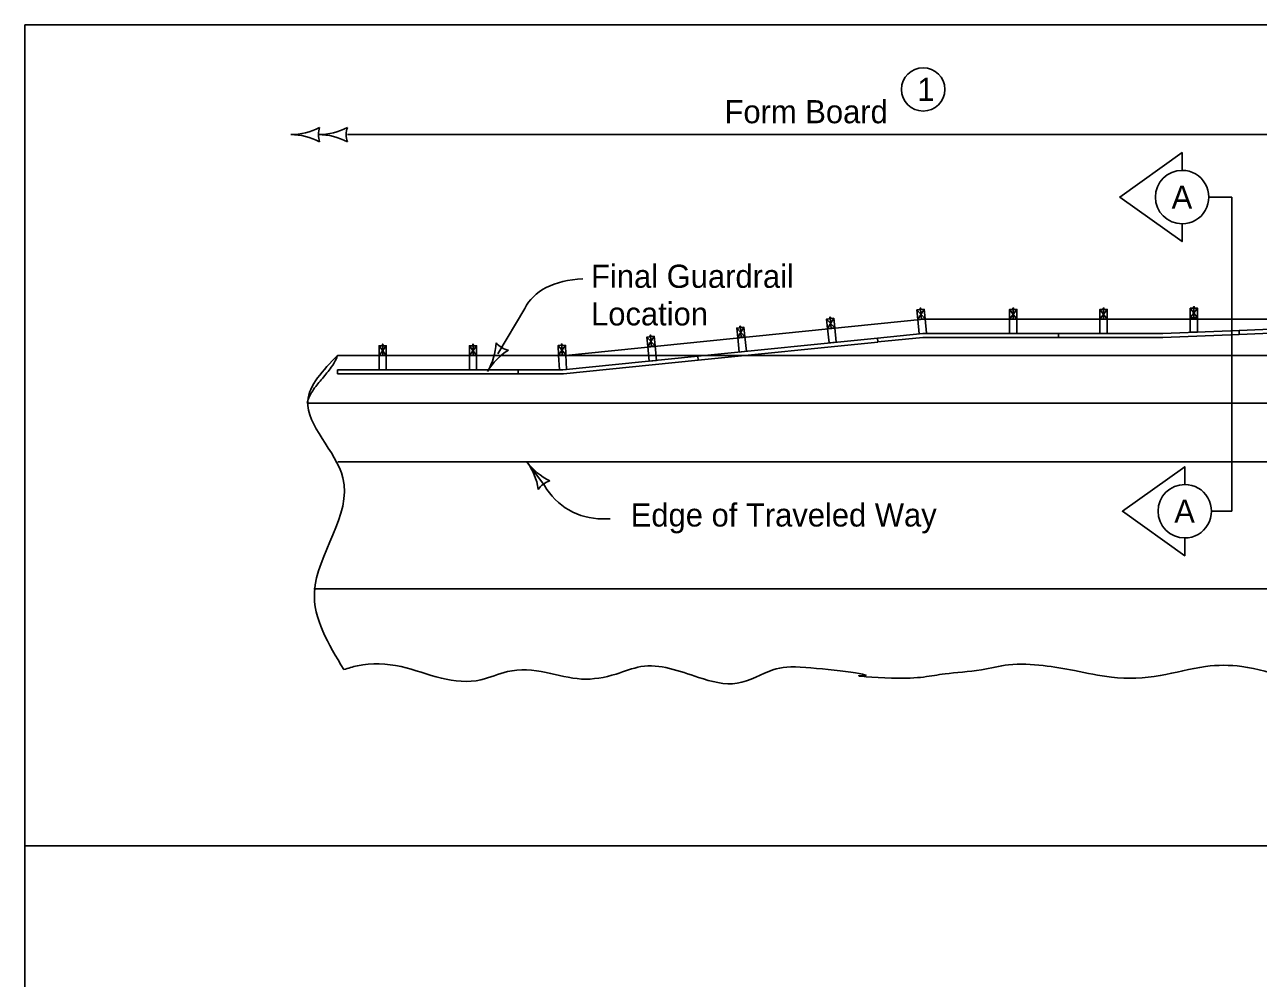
# Model space of a CAD drawing. Extents: x 6410 to 81668, y 3928 to 11667.
# Drawn here: x 6410 to 7264, y 9265 to 9924 of the extents above; entities that cross this region are included whole.
import ezdxf

# ---------------------------------------------------------------- set-up
doc = ezdxf.new("R2010")
doc.units = 0
for name, color, linetype in [('dsnCellElements', 7, 'Continuous'), ('dsnNonPlotable', 7, 'Continuous'), ('dsnShtPlotShapeBatchPrint', 7, 'Continuous'), ('dsnStdBlockModified', 7, 'Continuous'), ('Level 10', 7, 'Continuous'), ('Level 11', 7, 'Continuous'), ('Level 14', 7, 'Continuous'), ('Level 7', 7, 'Continuous')]:
    doc.layers.add(name, color=color, linetype=linetype)

msp = doc.modelspace()

# ---------------------------------------------------------------- linework, layer by layer
at = {"layer": 'dsnCellElements'}
for p, q in [((6756.43, 9728.01), (6737.88, 9696.66)), ((6756.43, 9728.01), (6737.88, 9696.66)), ((6770.05, 9605.55), (6757.93, 9622)), ((6770.05, 9605.55), (6757.93, 9622)), ((6810.13, 9582.48), (6815.58, 9582.48)), ((6810.13, 9582.48), (6815.58, 9582.48))]:
    msp.add_line(p, q, dxfattribs=at)
for centre, radius, start, end in [((6694.12, 9706.16), 42.5, 329.37973, 357.45222), ((6694.12, 9706.16), 42.5, 329.37973, 357.45222), ((6767.26, 9662.87), 42.5, 121.30724, 149.37973), ((6767.26, 9662.87), 42.5, 121.30724, 149.37973), ((6748.84, 9715.18), 16.42, 221.64638, 257.11308), ((6748.84, 9715.18), 16.42, 221.64638, 257.11308), ((6792.15, 9647.21), 42.5, 216.37256, 244.44505), ((6723.71, 9596.8), 42.5, 8.30007, 36.37256), ((6792.15, 9647.21), 42.5, 216.37256, 244.44505), ((6723.71, 9596.8), 42.5, 8.30007, 36.37256), ((6779.07, 9593.31), 16.42, 108.63921, 144.10591), ((6779.07, 9593.31), 16.42, 108.63921, 144.10591), ((6810.19, 9628.94), 46.46, 210.22743, 270), ((6810.19, 9628.94), 46.46, 210.22743, 270)]:
    msp.add_arc(centre, radius, start, end, dxfattribs=at)
msp.add_ellipse((6837.52, 9688.96), major_axis=(-81.09, 39.04), ratio=0.555556, start_param=5.482641, end_param=6.283185, dxfattribs=at)
msp.add_ellipse((6837.52, 9688.96), major_axis=(-81.09, 39.04), ratio=0.555556, start_param=5.482641, end_param=6.283185, dxfattribs=at)
at = {"layer": 'dsnNonPlotable'}
for q in [(6410.45, 8314.36), (9506.14, 9924.36)]:
    msp.add_line((6410.45, 9924.36), q, dxfattribs=at)
at = {"layer": 'dsnShtPlotShapeBatchPrint'}
msp.add_line((6633.72, 9848.49), (7656.14, 9848.49), dxfattribs=at)
msp.add_line((6633.72, 9848.49), (7656.14, 9848.49), dxfattribs=at)
for centre, radius, start, end in [((6594.5, 9890.84), 42.5, 270, 298.07249), ((6594.5, 9890.84), 42.5, 270, 298.07249), ((6613.72, 9890.84), 42.5, 270, 298.07249), ((6630.14, 9848.34), 16.42, 162.26665, 197.73335), ((6613.72, 9890.84), 42.5, 270, 298.07249), ((6630.14, 9848.34), 16.42, 162.26665, 197.73335), ((6649.36, 9848.34), 16.42, 162.26665, 197.73335), ((6649.36, 9848.34), 16.42, 162.26665, 197.73335), ((6594.5, 9805.84), 42.5, 61.92751, 90), ((6594.5, 9805.84), 42.5, 61.92751, 90), ((6613.72, 9805.84), 42.5, 61.92751, 90), ((6613.72, 9805.84), 42.5, 61.92751, 90)]:
    msp.add_arc(centre, radius, start, end, dxfattribs=at)
at = {"layer": 'dsnStdBlockModified'}
for p, q in [((7662.23, 9729.27), (7250.66, 9712.81)), ((7662.34, 9726.57), (7250.66, 9710.1)), ((6784.66, 9695.63), (7032.45, 9720.71)), ((7280.29, 9720.71), (7032.45, 9720.71)), ((7250.66, 9712.81), (7197.9, 9710.7)), ((7250.77, 9710.11), (7197.92, 9707.99)), ((7250.66, 9712.81), (7250.77, 9710.11)), ((7250.66, 9712.81), (7250.77, 9710.11)), ((6626.92, 9695.63), (6784.66, 9695.63)), ((6626.92, 9695.63), (7759.02, 9695.63)), ((6605.92, 9662.65), (8253.39, 9662.65)), ((7759.02, 9662.65), (6605.92, 9662.65)), ((6627.13, 9622), (8240.92, 9622))]:
    msp.add_line(p, q, dxfattribs=at)
for points in [[(6626.92, 9695.63), (6606.27, 9664.08), (6630.63, 9611), (6610.93, 9531.9), (6631.21, 9478.29)], [(6605.92, 9662.65), (6606.27, 9664.08), (6607.95, 9668.15), (6610.36, 9672.07), (6616.43, 9679.69), (6622.57, 9687.38), (6626.1, 9693.49), (6626.92, 9695.63)], [(6631.21, 9478.29), (6640.63, 9480.86), (6670.85, 9480.29), (6698.79, 9472.31), (6726.17, 9471.16), (6744.41, 9476.87), (6771.21, 9476.3), (6795.73, 9471.74), (6819.68, 9475.16), (6836.79, 9480.29), (6876.71, 9472.88), (6903.51, 9468.88), (6928.03, 9478.01), (6950.84, 9479.72), (6989.61, 9474.02), (6989.04, 9474.02), (7010.2, 9472.41), (7047.26, 9475.27), (7072.35, 9478.12), (7091.17, 9481.54), (7115.12, 9480.97), (7136.79, 9477.55), (7162.45, 9472.98), (7196.09, 9474.13), (7227.45, 9480.4), (7252.54, 9480.4), (7284.48, 9472.98), (7313.56, 9470.13), (7347.2, 9476.98), (7379.7, 9480.4), (7413.92, 9473.55), (7439.58, 9470.7), (7461.82, 9474.13), (7489.76, 9489.53), (7500.02, 9491.81), (7524.54, 9494.09), (7555.21, 9494.66), (7576.3, 9494.66), (7629.61, 9485.38)]]:
    msp.add_spline(points, degree=3, dxfattribs=at)
at = {"layer": 'Level 10'}
for p, q in [((7245.54, 9805.1), (7229.76, 9805.1)), ((7245.54, 9805.1), (7229.76, 9805.1)), ((7245.54, 9587.81), (7245.54, 9805.1)), ((7245.54, 9587.81), (7245.54, 9805.1)), ((7245.54, 9587.81), (7231.58, 9587.81)), ((7245.54, 9587.81), (7231.58, 9587.81))]:
    msp.add_line(p, q, dxfattribs=at)
for points in [[(7211.28, 9823.58), (7211.28, 9835.91), (7168.14, 9805.1), (7211.28, 9774.29), (7211.28, 9786.61)], [(7213.1, 9606.3), (7213.1, 9618.62), (7169.96, 9587.81), (7213.1, 9557), (7213.1, 9569.33)]]:
    msp.add_lwpolyline(points, dxfattribs=at)
for centre, start, end in [((7211.28, 9805.1), 90.00083, 269.99917), ((7211.28, 9805.1), 269.99917, 90.00083), ((7213.1, 9587.81), 90.00083, 269.99917), ((7213.1, 9587.81), 269.99917, 90.00083)]:
    msp.add_arc(centre, 18.49, start, end, dxfattribs=at)
at = {"layer": 'Level 11'}
for p, q in [((7032.45, 9720.71), (6784.66, 9695.63)), ((7283.63, 9720.71), (7032.45, 9720.71)), ((6784.66, 9695.63), (7759.02, 9695.63)), ((7816.57, 9695.63), (6784.66, 9695.63)), ((6610.53, 9534.09), (8252.57, 9534.09)), ((8566.03, 9356.36), (6410.45, 9356.36))]:
    msp.add_line(p, q, dxfattribs=at)
at = {"layer": 'Level 14'}
for p, q in [((6967.69, 9721.98), (6967.68, 9722.05)), ((7027.76, 9727.04), (7033.4, 9720.91)), ((7032.74, 9727.54), (7028.43, 9720.41)), ((7030.15, 9728.26), (7030.15, 9728.33)), ((7030.91, 9720.66), (7030.25, 9727.29)), ((7091.91, 9727.37), (7096.91, 9720.71)), ((7096.91, 9727.37), (7091.91, 9720.71)), ((7094.41, 9728.35), (7094.41, 9728.42)), ((7094.41, 9720.71), (7094.41, 9727.37)), ((7154.41, 9727.37), (7159.41, 9720.71)), ((7159.41, 9727.37), (7154.41, 9720.71)), ((7156.91, 9728.35), (7156.91, 9728.42)), ((7156.91, 9720.71), (7156.91, 9727.37)), ((7216.91, 9728.24), (7221.91, 9721.57)), ((7221.91, 9728.24), (7216.91, 9721.57)), ((7219.41, 9729.21), (7219.41, 9729.28)), ((7219.41, 9721.57), (7219.41, 9728.24)), ((6903.11, 9714.51), (6908.75, 9708.38)), ((6908.09, 9715.01), (6903.78, 9707.88)), ((6905.5, 9715.73), (6905.5, 9715.8)), ((6906.27, 9708.13), (6905.6, 9714.76)), ((6965.3, 9720.76), (6970.94, 9714.63)), ((6970.27, 9721.26), (6965.97, 9714.13)), ((6965.97, 9714.13), (6970.94, 9714.63)), ((6966.97, 9704.17), (6965.97, 9714.13)), ((6968.45, 9714.38), (6967.79, 9721.01)), ((6970.94, 9714.63), (6971.95, 9704.67)), ((7028.43, 9720.41), (7033.41, 9720.91)), ((7030.92, 9720.66), (7028.43, 9720.41)), ((7030.92, 9720.66), (7028.43, 9720.41)), ((7029.42, 9710.45), (7028.43, 9720.41)), ((7033.41, 9720.91), (7034.4, 9710.95)), ((7091.91, 9720.71), (7096.91, 9720.71)), ((7091.91, 9710.7), (7091.91, 9720.71)), ((7096.91, 9720.71), (7096.91, 9710.7)), ((7154.41, 9720.71), (7159.42, 9720.71)), ((7154.41, 9710.7), (7154.41, 9720.71)), ((7159.42, 9720.71), (7159.42, 9710.7)), ((7216.91, 9721.57), (7221.92, 9721.57)), ((7216.91, 9711.56), (7216.91, 9721.57)), ((7221.92, 9721.57), (7221.92, 9711.56)), ((6840.93, 9708.3), (6846.57, 9702.13)), ((6845.91, 9708.8), (6841.6, 9701.63)), ((6843.33, 9709.52), (6843.32, 9709.59)), ((6844.09, 9701.88), (6843.42, 9708.55)), ((6876.18, 9695.05), (7000.55, 9707.55)), ((6876.45, 9692.35), (7000.82, 9704.85)), ((6903.78, 9707.88), (6908.76, 9708.38)), ((6904.78, 9697.92), (6903.78, 9707.88)), ((6908.76, 9708.38), (6909.76, 9698.42)), ((7031.91, 9710.7), (7000.55, 9707.55)), ((7000.82, 9704.85), (7000.55, 9707.55)), ((7000.82, 9704.87), (7000.55, 9707.55)), ((7031.91, 9707.99), (7000.82, 9704.87)), ((7034.4, 9710.95), (7029.42, 9710.45)), ((7031.91, 9710.7), (7125.66, 9710.7)), ((7031.91, 9707.99), (7125.66, 9707.99)), ((7096.91, 9710.7), (7091.91, 9710.7)), ((7125.66, 9707.99), (7125.66, 9710.7)), ((7125.66, 9710.7), (7197.9, 9710.7)), ((7125.66, 9707.99), (7125.66, 9710.7)), ((7125.66, 9707.99), (7197.92, 9707.99)), ((7159.42, 9710.7), (7154.41, 9710.7)), ((7221.92, 9711.56), (7216.91, 9711.56)), ((6655.67, 9702.3), (6660.67, 9695.63)), ((6660.67, 9702.3), (6655.67, 9695.63)), ((6658.17, 9703.27), (6658.17, 9703.34)), ((6658.17, 9695.63), (6658.17, 9702.3)), ((6718.17, 9702.3), (6723.17, 9695.63)), ((6723.17, 9702.3), (6718.17, 9695.63)), ((6720.67, 9703.27), (6720.67, 9703.34)), ((6720.67, 9695.63), (6720.67, 9702.3)), ((6779.56, 9702.36), (6784.88, 9695.92)), ((6784.55, 9702.61), (6779.89, 9695.67)), ((6782.01, 9703.46), (6782, 9703.53)), ((6782.39, 9695.8), (6782.05, 9702.49)), ((6841.6, 9701.63), (6846.58, 9702.13)), ((6842.59, 9691.63), (6841.6, 9701.63)), ((6846.58, 9702.13), (6847.57, 9692.13)), ((6909.76, 9698.42), (6904.78, 9697.92)), ((6971.95, 9704.67), (6966.97, 9704.17)), ((6655.67, 9695.63), (6660.67, 9695.63)), ((6655.67, 9685.63), (6655.67, 9695.63)), ((6660.67, 9695.63), (6660.67, 9685.63)), ((6718.17, 9695.63), (6723.17, 9695.63)), ((6718.17, 9685.63), (6718.17, 9695.63)), ((6723.17, 9695.63), (6723.17, 9685.63)), ((6779.89, 9695.67), (6784.89, 9695.92)), ((6780.39, 9685.63), (6779.89, 9695.67)), ((6782.9, 9685.63), (6876.18, 9695.05)), ((6783.17, 9682.92), (6876.45, 9692.34)), ((6784.89, 9695.92), (6785.38, 9685.88)), ((6847.57, 9692.13), (6842.59, 9691.63)), ((6876.45, 9692.34), (6876.18, 9695.05)), ((6876.45, 9692.35), (6876.18, 9695.05)), ((6626.92, 9685.63), (6751.92, 9685.63)), ((6626.92, 9682.92), (6626.92, 9685.63)), ((6626.92, 9682.92), (6751.92, 9682.92)), ((6660.67, 9685.63), (6655.67, 9685.63)), ((6723.17, 9685.63), (6718.17, 9685.63)), ((6751.92, 9685.63), (6782.9, 9685.63)), ((6751.92, 9682.92), (6751.92, 9685.63)), ((6751.92, 9682.92), (6783.17, 9682.92)), ((6785.38, 9685.88), (6780.39, 9685.63))]:
    msp.add_line(p, q, dxfattribs=at)
for points in [[(6967.55, 9721.42), (6967.5, 9721.96), (6967.88, 9722), (6967.94, 9721.46)], [(7029.92, 9727.26), (7029.88, 9727.69), (7030.54, 9727.75), (7030.58, 9727.32)], [(7030.01, 9727.7), (7029.96, 9728.24), (7030.35, 9728.28), (7030.4, 9727.74)], [(7094.08, 9727.37), (7094.08, 9727.81), (7094.74, 9727.81), (7094.74, 9727.37)], [(7094.22, 9727.81), (7094.22, 9728.35), (7094.6, 9728.35), (7094.6, 9727.81)], [(7156.58, 9727.37), (7156.58, 9727.81), (7157.25, 9727.81), (7157.25, 9727.37)], [(7156.72, 9727.81), (7156.72, 9728.35), (7157.11, 9728.35), (7157.11, 9727.81)], [(7219.08, 9728.24), (7219.08, 9728.67), (7219.75, 9728.67), (7219.75, 9728.24)], [(7219.22, 9728.67), (7219.22, 9729.21), (7219.61, 9729.21), (7219.61, 9728.67)], [(6905.27, 9714.73), (6905.23, 9715.16), (6905.89, 9715.23), (6905.93, 9714.8)], [(6905.36, 9715.17), (6905.31, 9715.71), (6905.7, 9715.75), (6905.75, 9715.21)], [(6967.46, 9720.98), (6967.41, 9721.41), (6968.08, 9721.48), (6968.12, 9721.05)], [(6843.09, 9708.52), (6843.05, 9708.95), (6843.71, 9709.01), (6843.75, 9708.58)], [(6843.19, 9708.96), (6843.13, 9709.5), (6843.52, 9709.54), (6843.57, 9709)], [(6657.83, 9702.3), (6657.83, 9702.73), (6658.5, 9702.73), (6658.5, 9702.3)], [(6657.97, 9702.73), (6657.97, 9703.27), (6658.36, 9703.27), (6658.36, 9702.73)], [(6720.33, 9702.3), (6720.33, 9702.73), (6721, 9702.73), (6721, 9702.3)], [(6720.47, 9702.73), (6720.47, 9703.27), (6720.86, 9703.27), (6720.86, 9702.73)], [(6781.72, 9702.47), (6781.7, 9702.9), (6782.37, 9702.94), (6782.39, 9702.51)], [(6781.84, 9702.91), (6781.81, 9703.45), (6782.2, 9703.47), (6782.23, 9702.93)], [(6782.39, 9695.8), (6779.89, 9695.67), (6779.89, 9695.67)]]:
    msp.add_lwpolyline(points, dxfattribs=at)
for points in [[(7028.43, 9720.41), (7033.4, 9720.91), (7032.74, 9727.54), (7027.76, 9727.04)], [(7091.91, 9720.71), (7096.91, 9720.71), (7096.91, 9727.37), (7091.91, 9727.37)], [(7154.41, 9720.71), (7159.41, 9720.71), (7159.41, 9727.37), (7154.41, 9727.37)], [(7216.91, 9721.57), (7221.91, 9721.57), (7221.91, 9728.24), (7216.91, 9728.24)], [(6903.78, 9707.88), (6908.75, 9708.38), (6908.09, 9715.01), (6903.11, 9714.51)], [(6965.97, 9714.13), (6970.94, 9714.63), (6970.27, 9721.26), (6965.3, 9720.76)], [(6841.6, 9701.63), (6846.57, 9702.13), (6845.91, 9708.8), (6840.93, 9708.3)], [(6655.67, 9695.63), (6660.67, 9695.63), (6660.67, 9702.3), (6655.67, 9702.3)], [(6718.17, 9695.63), (6723.17, 9695.63), (6723.17, 9702.3), (6718.17, 9702.3)], [(6779.89, 9695.67), (6784.88, 9695.92), (6784.55, 9702.61), (6779.56, 9702.36)]]:
    msp.add_lwpolyline(points, close=True, dxfattribs=at)
at = {"layer": 'Level 7'}
msp.add_circle((7032.12, 9879.62), 15, dxfattribs=at)

# ---------------------------------------------------------------- texts
at = {"layer": 'dsnCellElements'}
for s, p in [('Final Guardrail ', (6802.33, 9742.33)), ('Final Guardrail ', (6802.33, 9742.33)), ('Location', (6802.33, 9716.33)), ('Location', (6802.33, 9716.33)), ('Edge of Traveled Way', (6829.77, 9577.21)), ('Edge of Traveled Way', (6829.77, 9577.21))]:
    msp.add_text(s, height=16, dxfattribs=at).set_placement(p)
at = {"layer": 'dsnShtPlotShapeBatchPrint'}
msp.add_text('Form Board', height=16, dxfattribs=at).set_placement((6894.67, 9856.18))
msp.add_text('Form Board', height=16, dxfattribs=at).set_placement((6894.67, 9856.18))
at = {"layer": 'Level 10'}
for p in [(7204, 9797.1), (7205.82, 9579.81)]:
    msp.add_text('A', height=16, dxfattribs=at).set_placement(p)
at = {"layer": 'Level 7'}
msp.add_text('1', height=16, dxfattribs=at).set_placement((7028.04, 9871.62))

doc.saveas('drawing.dxf')
